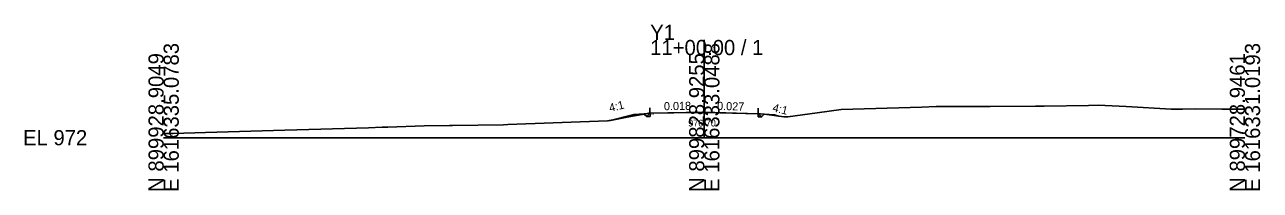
# Model space of a CAD drawing. Extents: x -26 to 203, y -10 to 2022.
# Drawn here: x -25.7 to 202.8, y 990.3 to 1020.8 of the extents above; entities that cross this region are included whole.
import ezdxf

# ---------------------------------------------------------------- set-up
doc = ezdxf.new("R2010")
doc.units = 0
for name, color, linetype in [('Exist Cross Section Cell', 7, 'Continuous'), ('Exist XS Center Line Elevation Label', 7, 'Continuous'), ('Exist XS Ground Line', 7, 'Continuous'), ('Prop XS Ditch Slope Text', 7, 'Continuous'), ('Prop XS Dump Level', 7, 'Continuous'), ('Prop XS Earthwork Shape', 7, 'Continuous'), ('Prop XS EOT Tick Mark', 7, 'Continuous'), ('Prop XS Finish Grade', 7, 'Continuous'), ('Prop XS Finish Grade Earthwork', 7, 'Continuous'), ('Prop XS Finish Grade Pavement', 7, 'Continuous'), ('Prop XS Pvmt Edge Slope', 7, 'Continuous'), ('Prop XS SE Text', 7, 'Continuous'), ('Prop XS Subgrade Earthwork', 7, 'Continuous')]:
    doc.layers.add(name, color=color, linetype=linetype)

msp = doc.modelspace()

# ---------------------------------------------------------------- linework, layer by layer
at = {"layer": 'Exist Cross Section Cell'}
for p, q in [((100, 1000), (100, 1018.04)), ((0, 1000), (100, 1000)), ((100, 1000), (200, 1000))]:
    msp.add_line(p, q, dxfattribs=at)
at = {"layer": 'Exist XS Ground Line'}
for p, q in [((125.31, 1005.22), (140.23, 1005.66)), ((140.23, 1005.66), (142.87, 1005.74)), ((142.87, 1005.74), (151.48, 1005.76)), ((151.48, 1005.76), (152.87, 1005.76)), ((152.87, 1005.76), (161.28, 1005.84)), ((161.28, 1005.84), (162.88, 1005.85)), ((162.88, 1005.85), (171.09, 1005.97)), ((171.09, 1005.97), (172.88, 1006.01)), ((172.88, 1006.01), (178.05, 1005.76)), ((178.05, 1005.76), (186.36, 1005.27)), ((82.13, 1003.09), (86.03, 1003.83)), ((86.03, 1003.83), (89.08, 1004.41)), ((89.08, 1004.41), (89.74, 1004.51)), ((89.74, 1004.51), (98.99, 1004.68)), ((98.99, 1004.68), (99.94, 1004.7)), ((99.94, 1004.7), (100.48, 1004.68)), ((100.48, 1004.68), (109.94, 1004.43)), ((109.94, 1004.43), (110.37, 1004.4)), ((110.37, 1004.4), (111.11, 1004.32)), ((111.11, 1004.32), (114.73, 1003.86)), ((114.73, 1003.86), (115.48, 1003.86)), ((115.48, 1003.86), (120.9, 1004.61)), ((120.9, 1004.61), (125.31, 1005.22)), ((186.36, 1005.27), (188.48, 1005.29)), ((188.48, 1005.29), (190.91, 1005.31)), ((190.91, 1005.31), (195.7, 1005.26)), ((195.7, 1005.26), (196.36, 1005.25)), ((196.36, 1005.25), (199.32, 1005.28)), ((199.32, 1005.28), (200, 1005.28)), ((7.75, 1000.96), (22.39, 1001.39)), ((22.39, 1001.39), (37.92, 1001.85)), ((37.92, 1001.85), (40.42, 1001.93)), ((40.42, 1001.93), (41.48, 1001.94)), ((41.48, 1001.94), (48.2, 1002.19)), ((48.2, 1002.19), (52.85, 1002.25)), ((52.85, 1002.25), (53.45, 1002.26)), ((53.45, 1002.26), (62.85, 1002.4)), ((62.85, 1002.4), (63.67, 1002.42)), ((63.67, 1002.42), (82.13, 1003.09)), ((0, 1000.76), (0.66, 1000.76)), ((0.66, 1000.76), (1.78, 1000.77)), ((1.78, 1000.77), (7.75, 1000.96))]:
    msp.add_line(p, q, dxfattribs=at)
at = {"layer": 'Prop XS Dump Level'}
for p, q in [((89.96, 1004.51), (100, 1004.7)), ((100, 1004.7), (109.99, 1004.43))]:
    msp.add_line(p, q, dxfattribs=at)
at = {"layer": 'Prop XS Earthwork Shape'}
for points in [[(86.96, 1004.28), (82.32, 1003.12), (86.03, 1003.83), (88.91, 1004.37), (88.86, 1004.43)], [(89.96, 1004.51), (89.36, 1003.92), (88.91, 1004.37), (89.08, 1004.41), (89.56, 1004.48)], [(89.96, 1003.93), (89.36, 1003.92), (89.96, 1004.51), (89.98, 1004.51), (89.97, 1003.93)], [(89.96, 1004.51), (89.56, 1004.48), (89.74, 1004.51)], [(109.99, 1004.43), (110.41, 1004.39), (111.08, 1004.32), (110.59, 1003.83)], [(110.37, 1004.4), (110.41, 1004.39), (109.99, 1004.43)], [(109.99, 1003.84), (109.99, 1004.43), (110.59, 1003.83)], [(111.1, 1004.34), (112.99, 1004.19), (113.81, 1003.98), (111.11, 1004.32), (111.08, 1004.32)]]:
    msp.add_lwpolyline(points, close=True, dxfattribs=at)
at = {"layer": 'Prop XS EOT Tick Mark'}
for p, q in [((89.96, 1004.51), (89.96, 1005.51)), ((109.99, 1004.43), (109.99, 1005.43))]:
    msp.add_line(p, q, dxfattribs=at)
at = {"layer": 'Prop XS Finish Grade'}
for p, q in [((89.96, 1004.51), (88.86, 1004.43)), ((109.99, 1004.43), (111.1, 1004.34))]:
    msp.add_line(p, q, dxfattribs=at)
at = {"layer": 'Prop XS Finish Grade Earthwork'}
for p, q in [((86.96, 1004.28), (82.32, 1003.12)), ((88.86, 1004.43), (86.96, 1004.28)), ((111.1, 1004.34), (112.99, 1004.19)), ((112.99, 1004.19), (113.81, 1003.98))]:
    msp.add_line(p, q, dxfattribs=at)
at = {"layer": 'Prop XS Finish Grade Pavement'}
for p, q in [((89.96, 1004.51), (100, 1004.7)), ((100, 1004.7), (109.99, 1004.43))]:
    msp.add_line(p, q, dxfattribs=at)
at = {"layer": 'Prop XS Pvmt Edge Slope'}
for p, q in [((89.96, 1004.51), (89.36, 1003.92)), ((109.99, 1004.43), (110.59, 1003.83))]:
    msp.add_line(p, q, dxfattribs=at)
at = {"layer": 'Prop XS Subgrade Earthwork'}
for p, q in [((89.36, 1003.92), (88.86, 1004.43)), ((89.96, 1003.93), (89.36, 1003.92)), ((89.97, 1003.93), (89.96, 1003.93)), ((89.97, 1003.93), (89.98, 1004.52)), ((109.99, 1003.84), (109.99, 1004.43)), ((109.99, 1003.84), (109.99, 1003.84)), ((109.99, 1003.84), (110.59, 1003.83)), ((110.59, 1003.83), (111.1, 1004.34))]:
    msp.add_line(p, q, dxfattribs=at)

# ---------------------------------------------------------------- texts
at = {"layer": 'Exist Cross Section Cell'}
for s, p in [('Y1', (90, 1018.04)), ('11+00.00 / 1', (90, 1015.24)), ('EL 972', (-26, 998.6))]:
    msp.add_text(s, height=2.8, dxfattribs=at).set_placement(p)
for s, p in [('E 1616335.0783', (2.8, 990)), ('E 1616333.0488', (102.8, 990)), ('E 1616331.0193', (202.8, 990)), ('N 899928.9049', (0, 990)), ('N 899828.9255', (100, 990)), ('N 899728.9461', (200, 990))]:
    msp.add_text(s, height=2.8, rotation=90, dxfattribs=at).set_placement(p)
at = {"layer": 'Exist XS Center Line Elevation Label'}
msp.add_text('976.70', height=1.25, dxfattribs=at).set_placement((97.02, 1002.07))
at = {"layer": 'Prop XS Ditch Slope Text'}
for rotation, p in [(14.0362, (82.59, 1004.74)), (345.9638, (112.53, 1004.89))]:
    msp.add_text('4:1', height=1.5, rotation=rotation, dxfattribs=at).set_placement(p)
at = {"layer": 'Prop XS Dump Level'}
for s, height, p in [('Case1', 0.04, (86.96, 1004.24)), ('Eop', 0.3, (89.97, 1004.22)), ('Eop', 0.3, (109.99, 1004.13)), ('Case1', 0.04, (112.99, 1004.15))]:
    msp.add_text(s, height=height, dxfattribs=at).set_placement(p)
at = {"layer": 'Prop XS SE Text'}
for s, rotation, p in [('0.018', 1.0312, (92.55, 1005.06)), ('0.027', 358.4534, (102.36, 1005.13))]:
    msp.add_text(s, height=1.5, rotation=rotation, dxfattribs=at).set_placement(p)

doc.saveas('drawing.dxf')
